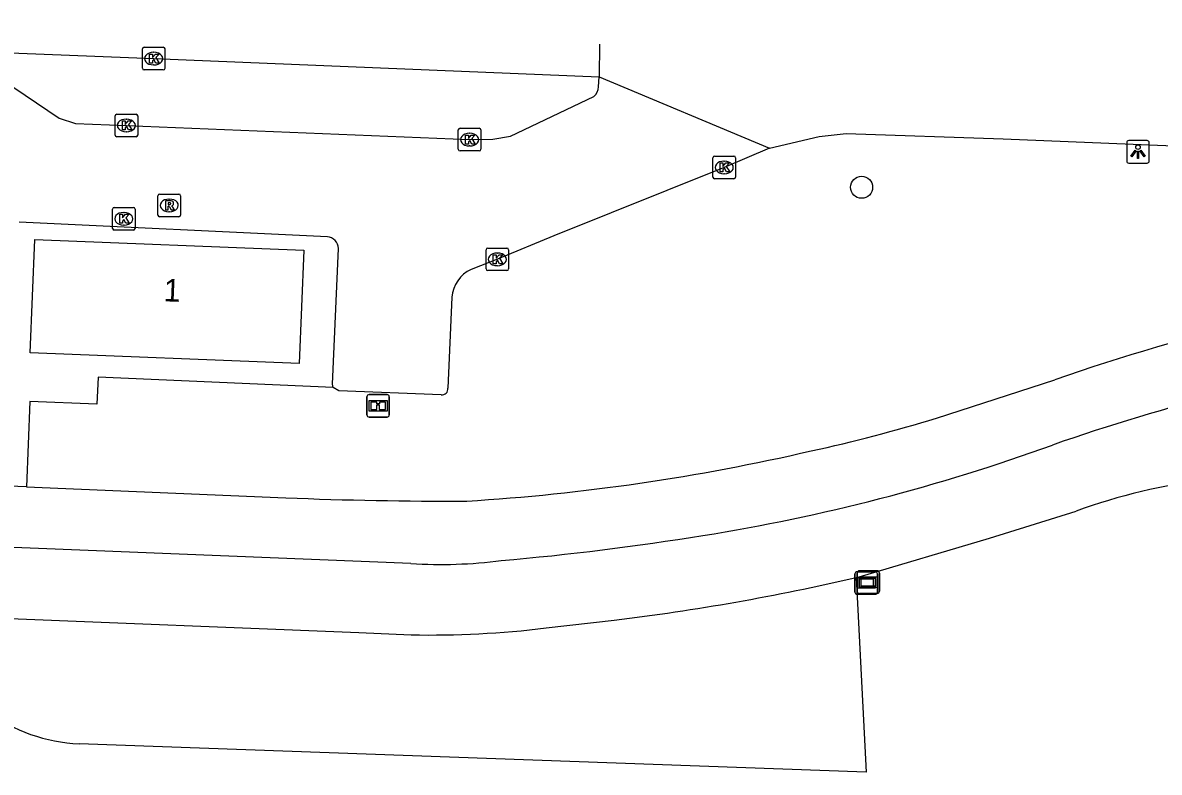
# Model space of a CAD drawing. Extents: x 161355 to 162026, y 386504 to 387459.
# Drawn here: x 161533.7 to 161584, y 387422.6 to 387455.8 of the extents above; entities that cross this region are included whole.
import ezdxf

# ---------------------------------------------------------------- set-up
doc = ezdxf.new("R2010")
doc.units = 0
for name, color, linetype in [('IMGEO_Boom', 7, 'Continuous'), ('IMGEO_Fietspad_gesloten', 7, 'Continuous'), ('IMGEO_Groenvoorziening', 7, 'Continuous'), ('IMGEO_Informatiebord', 7, 'Continuous'), ('IMGEO_Kolk', 7, 'Continuous'), ('IMGEO_Lichtpunt', 7, 'Continuous'), ('IMGEO_Pand', 7, 'Continuous'), ('IMGEO_Pand_nummerreeks', 7, 'Continuous'), ('IMGEO_Rijbaan_lokaal_gesloten', 7, 'Continuous'), ('IMGEO_Rijbaan_lokaal_open', 7, 'Continuous'), ('IMGEO_Rioolput', 7, 'Continuous'), ('IMGEO_Verklikker', 7, 'Continuous'), ('IMGEO_Voetpad_open', 7, 'Continuous')]:
    doc.layers.add(name, color=color, linetype=linetype)

msp = doc.modelspace()

# ---------------------------------------------------------------- linework, layer by layer
at = {"layer": 'IMGEO_Boom'}
msp.add_circle((161570.812, 387448.468), 0.489, dxfattribs=at)
at = {"layer": 'IMGEO_Fietspad_gesloten'}
for points in [[(161574.127, 387438.243), (161579.376, 387439.94)], [(161533.831, 387435.204), (161530.79, 387435.322)], [(161533.831, 387435.204), (161545.312, 387434.716)], [(161550.847, 387431.802), (161521.887, 387432.975)]]:
    msp.add_lwpolyline(points, dxfattribs=at)
for centre, radius, start, end in [((161607.624, 387359.522), 85.235, 96.67591, 109.35439), ((161611.973, 387342.556), 100, 104.50687, 109.09324), ((161554.056, 387503.774), 68.536, 282.23602, 287.02928), ((161547.601, 387527.315), 92.92, 273.53172, 283.04909), ((161550.488, 387516.332), 84.339, 279.07343, 289.94845), ((161552.503, 387611.857), 177.286, 267.67531, 270.26561), ((161543.396, 387560.142), 128.719, 275.10953, 279.11523), ((161552.118, 387454.054), 22.289, 266.7304, 277.066)]:
    msp.add_arc(centre, radius, start, end, dxfattribs=at)
at = {"layer": 'IMGEO_Groenvoorziening'}
msp.add_lwpolyline([(161570.572, 387431.189), (161570.704, 387428.601), (161571.014, 387422.564), (161536.168, 387423.823)], dxfattribs=at)
msp.add_arc((161536.51, 387431.29), 7.475, 233.6324, 267.3762, dxfattribs=at)
at = {"layer": 'IMGEO_Informatiebord'}
for p, q in [((161548.91, 387438.39), (161548.91, 387439.19)), ((161548.91, 387439.19), (161548.91, 387438.39)), ((161549.01, 387439.29), (161549.8, 387439.29)), ((161549.8, 387439.29), (161549.01, 387439.29)), ((161549.9, 387439.19), (161549.9, 387438.39)), ((161549.9, 387438.39), (161549.9, 387439.19)), ((161549.8, 387438.29), (161549.01, 387438.29)), ((161549.01, 387438.29), (161549.8, 387438.29))]:
    msp.add_line(p, q, dxfattribs=at)
for points in [[(161549.011, 387439.022), (161549.799, 387439.022), (161549.799, 387438.558), (161549.011, 387438.558), (161549.011, 387439.022)], [(161549.076, 387438.957), (161549.076, 387438.623), (161549.351, 387438.623), (161549.352, 387438.836), (161549.456, 387438.837), (161549.457, 387438.623), (161549.734, 387438.623), (161549.734, 387438.957), (161549.458, 387438.957), (161549.458, 387438.877), (161549.352, 387438.877), (161549.352, 387438.957), (161549.076, 387438.957)]]:
    msp.add_lwpolyline(points, dxfattribs=at)
for centre, start, end in [((161549.01, 387439.19), 90, 180), ((161549.01, 387439.19), 90, 180), ((161549.8, 387439.19), 0, 90), ((161549.8, 387439.19), 360, 90), ((161549.01, 387438.39), 180, 270), ((161549.01, 387438.39), 180, 270), ((161549.8, 387438.39), 270, 0), ((161549.8, 387438.39), 270, 0)]:
    msp.add_arc(centre, 0.1, start, end, dxfattribs=at)
at = {"layer": 'IMGEO_Kolk'}
for p, q in [((161538.965, 387453.739), (161538.965, 387454.591)), ((161539.04, 387454.665), (161539.892, 387454.665)), ((161539.453, 387454.445), (161539.478, 387454.445)), ((161539.966, 387454.591), (161539.966, 387453.739)), ((161539.476, 387453.885), (161539.451, 387453.885)), ((161539.892, 387453.665), (161539.04, 387453.665)), ((161537.832, 387451.703), (161538.684, 387451.703)), ((161537.757, 387450.777), (161537.757, 387451.629)), ((161538.245, 387451.483), (161538.27, 387451.483)), ((161538.758, 387451.629), (161538.758, 387450.777)), ((161538.684, 387450.703), (161537.832, 387450.703)), ((161538.268, 387450.923), (161538.243, 387450.923)), ((161552.955, 387450.152), (161552.955, 387451.004)), ((161553.03, 387451.078), (161553.882, 387451.078)), ((161553.443, 387450.858), (161553.468, 387450.858)), ((161553.956, 387451.004), (161553.956, 387450.152)), ((161553.466, 387450.298), (161553.441, 387450.298)), ((161553.882, 387450.078), (161553.03, 387450.078)), ((161564.231, 387448.918), (161564.231, 387449.77)), ((161564.306, 387449.844), (161565.158, 387449.844)), ((161565.232, 387449.77), (161565.232, 387448.918)), ((161564.719, 387449.624), (161564.744, 387449.624)), ((161565.158, 387448.844), (161564.306, 387448.844)), ((161564.742, 387449.064), (161564.717, 387449.064)), ((161537.642, 387446.645), (161537.642, 387447.497)), ((161537.717, 387447.571), (161538.569, 387447.571)), ((161538.13, 387447.351), (161538.155, 387447.351)), ((161538.643, 387447.497), (161538.643, 387446.645)), ((161538.153, 387446.791), (161538.128, 387446.791)), ((161538.569, 387446.571), (161537.717, 387446.571)), ((161554.183, 387444.849), (161554.183, 387445.701)), ((161554.258, 387445.775), (161555.11, 387445.775)), ((161555.184, 387445.701), (161555.184, 387444.849)), ((161554.671, 387445.555), (161554.696, 387445.555)), ((161555.11, 387444.775), (161554.258, 387444.775)), ((161554.694, 387444.995), (161554.669, 387444.995))]:
    msp.add_line(p, q, dxfattribs=at)
for points in [[(161538.965, 387453.739), (161538.965, 387454.591)], [(161539.04, 387454.665), (161539.892, 387454.665)], [(161539.286, 387454.365), (161539.409, 387454.365), (161539.409, 387454.214), (161539.539, 387454.365), (161539.703, 387454.365), (161539.557, 387454.214), (161539.71, 387453.965), (161539.558, 387453.965), (161539.473, 387454.129), (161539.409, 387454.062), (161539.409, 387453.965), (161539.286, 387453.965), (161539.286, 387454.365)], [(161539.966, 387454.591), (161539.966, 387453.739)], [(161539.892, 387453.665), (161539.04, 387453.665)], [(161537.832, 387451.703), (161538.684, 387451.703)], [(161537.757, 387450.777), (161537.757, 387451.629)], [(161538.078, 387451.403), (161538.201, 387451.403), (161538.201, 387451.252), (161538.331, 387451.403), (161538.495, 387451.403), (161538.349, 387451.252), (161538.502, 387451.003), (161538.35, 387451.003), (161538.265, 387451.167), (161538.201, 387451.1), (161538.201, 387451.003), (161538.078, 387451.003), (161538.078, 387451.403)], [(161538.758, 387451.629), (161538.758, 387450.777)], [(161538.684, 387450.703), (161537.832, 387450.703)], [(161552.955, 387450.152), (161552.955, 387451.004)], [(161553.03, 387451.078), (161553.882, 387451.078)], [(161553.276, 387450.778), (161553.399, 387450.778), (161553.399, 387450.627), (161553.529, 387450.778), (161553.693, 387450.778), (161553.547, 387450.627), (161553.7, 387450.378), (161553.548, 387450.378), (161553.463, 387450.542), (161553.399, 387450.475), (161553.399, 387450.378), (161553.276, 387450.378), (161553.276, 387450.778)], [(161553.956, 387451.004), (161553.956, 387450.152)], [(161553.882, 387450.078), (161553.03, 387450.078)], [(161564.231, 387448.918), (161564.231, 387449.77)], [(161564.306, 387449.844), (161565.158, 387449.844)], [(161565.232, 387449.77), (161565.232, 387448.918)], [(161564.552, 387449.544), (161564.675, 387449.544), (161564.675, 387449.393), (161564.805, 387449.544), (161564.969, 387449.544), (161564.823, 387449.393), (161564.976, 387449.144), (161564.824, 387449.144), (161564.739, 387449.308), (161564.675, 387449.241), (161564.675, 387449.144), (161564.552, 387449.144), (161564.552, 387449.544)], [(161565.158, 387448.844), (161564.306, 387448.844)], [(161537.642, 387446.645), (161537.642, 387447.497)], [(161537.717, 387447.571), (161538.569, 387447.571)], [(161537.963, 387447.271), (161538.086, 387447.271), (161538.086, 387447.12), (161538.216, 387447.271), (161538.38, 387447.271), (161538.234, 387447.12), (161538.387, 387446.871), (161538.235, 387446.871), (161538.15, 387447.035), (161538.086, 387446.968), (161538.086, 387446.871), (161537.963, 387446.871), (161537.963, 387447.271)], [(161538.643, 387447.497), (161538.643, 387446.645)], [(161538.569, 387446.571), (161537.717, 387446.571)], [(161554.183, 387444.849), (161554.183, 387445.701)], [(161554.258, 387445.775), (161555.11, 387445.775)], [(161555.184, 387445.701), (161555.184, 387444.849)], [(161554.504, 387445.475), (161554.627, 387445.475), (161554.627, 387445.324), (161554.757, 387445.475), (161554.921, 387445.475), (161554.775, 387445.324), (161554.928, 387445.075), (161554.776, 387445.075), (161554.691, 387445.239), (161554.627, 387445.172), (161554.627, 387445.075), (161554.504, 387445.075), (161554.504, 387445.475)], [(161555.11, 387444.775), (161554.258, 387444.775)]]:
    msp.add_lwpolyline(points, dxfattribs=at)
for centre, start, end in [((161539.042, 387454.589), 91.552, 178.448), ((161539.042, 387454.589), 91.552, 178.448), ((161539.89, 387454.589), 1.552, 88.448), ((161539.89, 387454.589), 1.552, 88.448), ((161539.042, 387453.741), 181.552, 268.448), ((161539.042, 387453.741), 181.552, 268.448), ((161539.89, 387453.741), 271.552, 358.448), ((161539.89, 387453.741), 271.552, 358.448), ((161537.834, 387451.627), 91.552, 178.448), ((161537.834, 387451.627), 91.552, 178.448), ((161538.682, 387451.627), 1.552, 88.448), ((161538.682, 387451.627), 1.552, 88.448), ((161537.834, 387450.779), 181.552, 268.448), ((161537.834, 387450.779), 181.552, 268.448), ((161538.682, 387450.779), 271.552, 358.448), ((161538.682, 387450.779), 271.552, 358.448), ((161553.032, 387451.002), 91.552, 178.448), ((161553.032, 387451.002), 91.552, 178.448), ((161553.88, 387451.002), 1.552, 88.448), ((161553.88, 387451.002), 1.552, 88.448), ((161553.032, 387450.154), 181.552, 268.448), ((161553.032, 387450.154), 181.552, 268.448), ((161553.88, 387450.154), 271.552, 358.448), ((161553.88, 387450.154), 271.552, 358.448), ((161564.308, 387449.768), 91.552, 178.448), ((161564.308, 387449.768), 91.552, 178.448), ((161565.156, 387449.768), 1.552, 88.448), ((161565.156, 387449.768), 1.552, 88.448), ((161564.308, 387448.92), 181.552, 268.448), ((161564.308, 387448.92), 181.552, 268.448), ((161565.156, 387448.92), 271.552, 358.448), ((161565.156, 387448.92), 271.552, 358.448), ((161537.719, 387447.495), 91.552, 178.448), ((161537.719, 387447.495), 91.552, 178.448), ((161538.567, 387447.495), 1.552, 88.448), ((161538.567, 387447.495), 1.552, 88.448), ((161537.719, 387446.647), 181.552, 268.448), ((161537.719, 387446.647), 181.552, 268.448), ((161538.567, 387446.647), 271.552, 358.448), ((161538.567, 387446.647), 271.552, 358.448), ((161554.26, 387445.699), 91.552, 178.448), ((161554.26, 387445.699), 91.552, 178.448), ((161555.108, 387445.699), 1.552, 88.448), ((161555.108, 387445.699), 1.552, 88.448), ((161554.26, 387444.851), 181.552, 268.448), ((161554.26, 387444.851), 181.552, 268.448), ((161555.108, 387444.851), 271.552, 358.448), ((161555.108, 387444.851), 271.552, 358.448)]:
    msp.add_arc(centre, 0.0765, start, end, dxfattribs=at)
for centre, major_axis, ratio, start_param, end_param in [((161539.452, 387454.165), (-0.387, 0.002), 0.722429, 4.712389, 7.853982), ((161539.477, 387454.165), (-0.39, 0.002), 0.717154, 1.570796, 4.712389), ((161538.244, 387451.203), (-0.387, 0.002), 0.722429, 4.712389, 7.853982), ((161538.269, 387451.203), (-0.39, 0.002), 0.717154, 1.570796, 4.712389), ((161553.442, 387450.578), (-0.387, 0.002), 0.722429, 4.712389, 7.853982), ((161553.467, 387450.578), (-0.39, 0.002), 0.717154, 1.570796, 4.712389), ((161564.718, 387449.344), (-0.387, 0.002), 0.722429, 4.712389, 7.853982), ((161564.743, 387449.344), (-0.39, 0.002), 0.717154, 1.570796, 4.712389), ((161538.129, 387447.071), (-0.387, 0.002), 0.722429, 4.712389, 7.853982), ((161538.154, 387447.071), (-0.39, 0.002), 0.717154, 1.570796, 4.712389), ((161554.67, 387445.275), (-0.387, 0.002), 0.722429, 4.712389, 7.853982), ((161554.695, 387445.275), (-0.39, 0.002), 0.717154, 1.570796, 4.712389)]:
    msp.add_ellipse(centre, major_axis=major_axis, ratio=ratio, start_param=start_param, end_param=end_param, dxfattribs=at)
at = {"layer": 'IMGEO_Lichtpunt'}
for p, q in [((161582.552, 387450.442), (161582.552, 387449.635)), ((161582.552, 387450.442), (161582.552, 387449.635)), ((161583.454, 387450.537), (161582.646, 387450.537)), ((161583.454, 387450.537), (161582.646, 387450.537)), ((161583.548, 387449.635), (161583.548, 387450.442)), ((161583.548, 387449.635), (161583.548, 387450.442)), ((161582.646, 387449.541), (161583.454, 387449.541)), ((161582.646, 387449.541), (161583.454, 387449.541))]:
    msp.add_line(p, q, dxfattribs=at)
for points in [[(161582.926, 387450.106), (161582.965, 387450.078), (161582.777, 387449.816), (161582.739, 387449.843), (161582.926, 387450.106)], [(161583.028, 387450.058), (161583.075, 387450.058), (161583.075, 387449.736), (161583.028, 387449.736), (161583.028, 387450.058)], [(161583.138, 387450.078), (161583.176, 387450.105), (161583.363, 387449.843), (161583.324, 387449.815), (161583.138, 387450.078)]]:
    msp.add_lwpolyline(points, dxfattribs=at)
msp.add_circle((161583.051, 387450.24), 0.0994, dxfattribs=at)
for centre, start, end in [((161582.646, 387450.442), 90, 180), ((161582.646, 387450.442), 90, 180), ((161583.454, 387450.442), 0, 90), ((161583.454, 387450.442), 0, 90), ((161582.646, 387449.635), 180, 270), ((161582.646, 387449.635), 180, 270), ((161583.454, 387449.635), 270, 0), ((161583.454, 387449.635), 270, 360)]:
    msp.add_arc(centre, 0.0946, start, end, dxfattribs=at)
at = {"layer": 'IMGEO_Pand'}
msp.add_lwpolyline([(161534.002, 387441.133), (161534.203, 387446.156), (161546.108, 387445.68), (161545.907, 387440.657), (161534.002, 387441.133)], dxfattribs=at)
at = {"layer": 'IMGEO_Rijbaan_lokaal_gesloten'}
for points in [[(161499.444, 387455.752), (161500, 387455.73), (161518.907, 387454.987), (161539.467, 387454.167), (161559.197, 387453.359)], [(161559.208, 387454.807), (161559.197, 387453.359)], [(161559.197, 387453.359), (161566.731, 387450.192)], [(161566.731, 387450.192), (161568.939, 387450.72), (161570.123, 387450.845), (161577.085, 387450.606), (161735.771, 387444.103), (161739.669, 387443.941)]]:
    msp.add_lwpolyline(points, dxfattribs=at)
at = {"layer": 'IMGEO_Rijbaan_lokaal_open'}
for points in [[(161522.54, 387453.825), (161532.045, 387453.475), (161532.773, 387453.217), (161535.278, 387451.524), (161536.01, 387451.288), (161538.258, 387451.202), (161553.456, 387450.577), (161554.487, 387450.593), (161555.262, 387450.735), (161558.952, 387452.485)], [(161559.157, 387452.919), (161559.197, 387453.359)], [(161566.731, 387450.192), (161564.732, 387449.345), (161557.191, 387446.309), (161554.684, 387445.276), (161553.519, 387444.83)], [(161547.156, 387446.275), (161533.502, 387446.923)], [(161547.418, 387439.598), (161547.383, 387439.755), (161547.644, 387445.754)], [(161552.67, 387443.599), (161552.486, 387439.573)], [(161552.197, 387439.281), (161547.67, 387439.458), (161547.418, 387439.598)]]:
    msp.add_lwpolyline(points, dxfattribs=at)
for centre, radius, start, end in [((161558.64, 387452.898), 0.517, 307.0689, 2.3637), ((161547.112, 387445.745), 0.532, 0.9659, 85.2876), ((161554.164, 387443.477), 1.499, 115.4762, 175.337), ((161552.24, 387439.528), 0.251, 260.2091, 10.3826)]:
    msp.add_arc(centre, radius, start, end, dxfattribs=at)
at = {"layer": 'IMGEO_Rioolput'}
for p, q in [((161539.728, 387448.162), (161540.58, 387448.162)), ((161539.653, 387447.236), (161539.653, 387448.088)), ((161540.141, 387447.942), (161540.166, 387447.942)), ((161540.654, 387448.088), (161540.654, 387447.236)), ((161540.58, 387447.162), (161539.728, 387447.162)), ((161540.164, 387447.382), (161540.139, 387447.382))]:
    msp.add_line(p, q, dxfattribs=at)
for points in [[(161539.728, 387448.162), (161540.58, 387448.162)], [(161539.653, 387447.236), (161539.653, 387448.088)], [(161540.242, 387447.86), (161539.99, 387447.862), (161539.99, 387447.462)], [(161540.168, 387447.781), (161540.114, 387447.781), (161540.114, 387447.7)], [(161540.114, 387447.7), (161540.166, 387447.7)], [(161540.654, 387448.088), (161540.654, 387447.236)], [(161540.58, 387447.162), (161539.728, 387447.162)], [(161539.99, 387447.462), (161540.114, 387447.462), (161540.114, 387447.624), (161540.125, 387447.624)], [(161540.172, 387447.595), (161540.243, 387447.462), (161540.383, 387447.462), (161540.318, 387447.588)]]:
    msp.add_lwpolyline(points, dxfattribs=at)
for centre, radius, start, end in [((161539.73, 387448.086), 0.0765, 91.552, 178.448), ((161539.73, 387448.086), 0.0765, 91.552, 178.448), ((161540.578, 387448.086), 0.0765, 1.552, 88.448), ((161540.578, 387448.086), 0.0765, 1.552, 88.448), ((161540.15, 387447.889), 0.19, 274.7715, 282.9687), ((161540.174, 387447.685), 0.0964, 77.0061, 93.1865), ((161540.188, 387447.742), 0.0378, 276.6634, 79.6772), ((161540.241, 387447.75), 0.109, 350.3612, 89.416), ((161540.239, 387447.75), 0.112, 277.5842, 350.9817), ((161539.73, 387447.238), 0.0765, 181.552, 268.448), ((161539.73, 387447.238), 0.0765, 181.552, 268.448), ((161540.124, 387447.571), 0.0533, 26.0293, 88.6989), ((161540.223, 387447.535), 0.108, 29.5134, 73.7905), ((161540.578, 387447.238), 0.0765, 271.552, 358.448), ((161540.578, 387447.238), 0.0765, 271.552, 358.448)]:
    msp.add_arc(centre, radius, start, end, dxfattribs=at)
for centre, major_axis, ratio, start_param, end_param in [((161540.14, 387447.662), (-0.387, 0.002), 0.722429, 4.712389, 7.853982), ((161540.165, 387447.662), (-0.39, 0.002), 0.717154, 1.570796, 4.712389)]:
    msp.add_ellipse(centre, major_axis=major_axis, ratio=ratio, start_param=start_param, end_param=end_param, dxfattribs=at)
at = {"layer": 'IMGEO_Verklikker'}
for p, q in [((161570.52, 387430.543), (161570.52, 387431.343)), ((161570.52, 387431.343), (161570.52, 387430.543)), ((161570.614, 387430.584), (161570.614, 387431.384)), ((161570.614, 387431.384), (161570.614, 387430.584)), ((161570.62, 387431.443), (161571.41, 387431.443)), ((161571.41, 387431.443), (161570.62, 387431.443)), ((161570.714, 387431.484), (161571.504, 387431.484)), ((161571.504, 387431.484), (161570.714, 387431.484)), ((161571.51, 387431.343), (161571.51, 387430.543)), ((161571.51, 387430.543), (161571.51, 387431.343)), ((161571.604, 387431.384), (161571.604, 387430.584)), ((161571.604, 387430.584), (161571.604, 387431.384)), ((161571.41, 387430.443), (161570.62, 387430.443)), ((161570.62, 387430.443), (161571.41, 387430.443)), ((161571.504, 387430.484), (161570.714, 387430.484)), ((161570.714, 387430.484), (161571.504, 387430.484))]:
    msp.add_line(p, q, dxfattribs=at)
for points in [[(161570.621, 387431.175), (161571.409, 387431.175), (161571.409, 387430.711), (161570.621, 387430.711), (161570.621, 387431.175)], [(161570.686, 387431.11), (161570.686, 387430.776), (161571.344, 387430.776), (161571.344, 387431.11), (161570.686, 387431.11)], [(161570.715, 387431.216), (161571.503, 387431.216), (161571.503, 387430.752), (161570.715, 387430.752), (161570.715, 387431.216)], [(161570.78, 387431.151), (161570.78, 387430.817), (161571.438, 387430.817), (161571.438, 387431.151), (161570.78, 387431.151)]]:
    msp.add_lwpolyline(points, dxfattribs=at)
for centre, start, end in [((161570.62, 387431.343), 90, 180), ((161570.62, 387431.343), 90, 180), ((161570.714, 387431.384), 90, 180), ((161570.714, 387431.384), 90, 180), ((161571.41, 387431.343), 0, 90), ((161571.41, 387431.343), 360, 90), ((161571.504, 387431.384), 0, 90), ((161571.504, 387431.384), 360, 90), ((161570.62, 387430.543), 180, 270), ((161570.62, 387430.543), 180, 270), ((161570.714, 387430.584), 180, 270), ((161570.714, 387430.584), 180, 270), ((161571.41, 387430.543), 270, 0), ((161571.41, 387430.543), 270, 0), ((161571.504, 387430.584), 270, 0), ((161571.504, 387430.584), 270, 0)]:
    msp.add_arc(centre, 0.1, start, end, dxfattribs=at)
at = {"layer": 'IMGEO_Voetpad_open'}
for points in [[(161547.418, 387439.598), (161537.003, 387440.057), (161536.952, 387438.857), (161533.986, 387438.978), (161533.831, 387435.204)], [(161570.572, 387431.189), (161570.641, 387431.205), (161570.709, 387431.221), (161576.48, 387432.929), (161580.316, 387434.128)], [(161532.339, 387429.397), (161548.547, 387428.759), (161550.868, 387428.648)], [(161556.848, 387428.953), (161559.855, 387429.305)]]:
    msp.add_lwpolyline(points, dxfattribs=at)
for centre, radius, start, end in [((161589.025, 387410.297), 25.373, 96.4297, 110.0753), ((161548.156, 387527.28), 98.671, 276.80959, 283.13134), ((161551.656, 387471.976), 43.335, 268.9582, 276.8813)]:
    msp.add_arc(centre, radius, start, end, dxfattribs=at)

# ---------------------------------------------------------------- texts
at = {"layer": 'IMGEO_Pand_nummerreeks'}
msp.add_text('1', height=1, rotation=357.7103, dxfattribs=at).set_placement((161539.894, 387443.42))

doc.saveas('drawing.dxf')
